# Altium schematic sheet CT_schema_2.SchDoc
size 314 x 312 mm
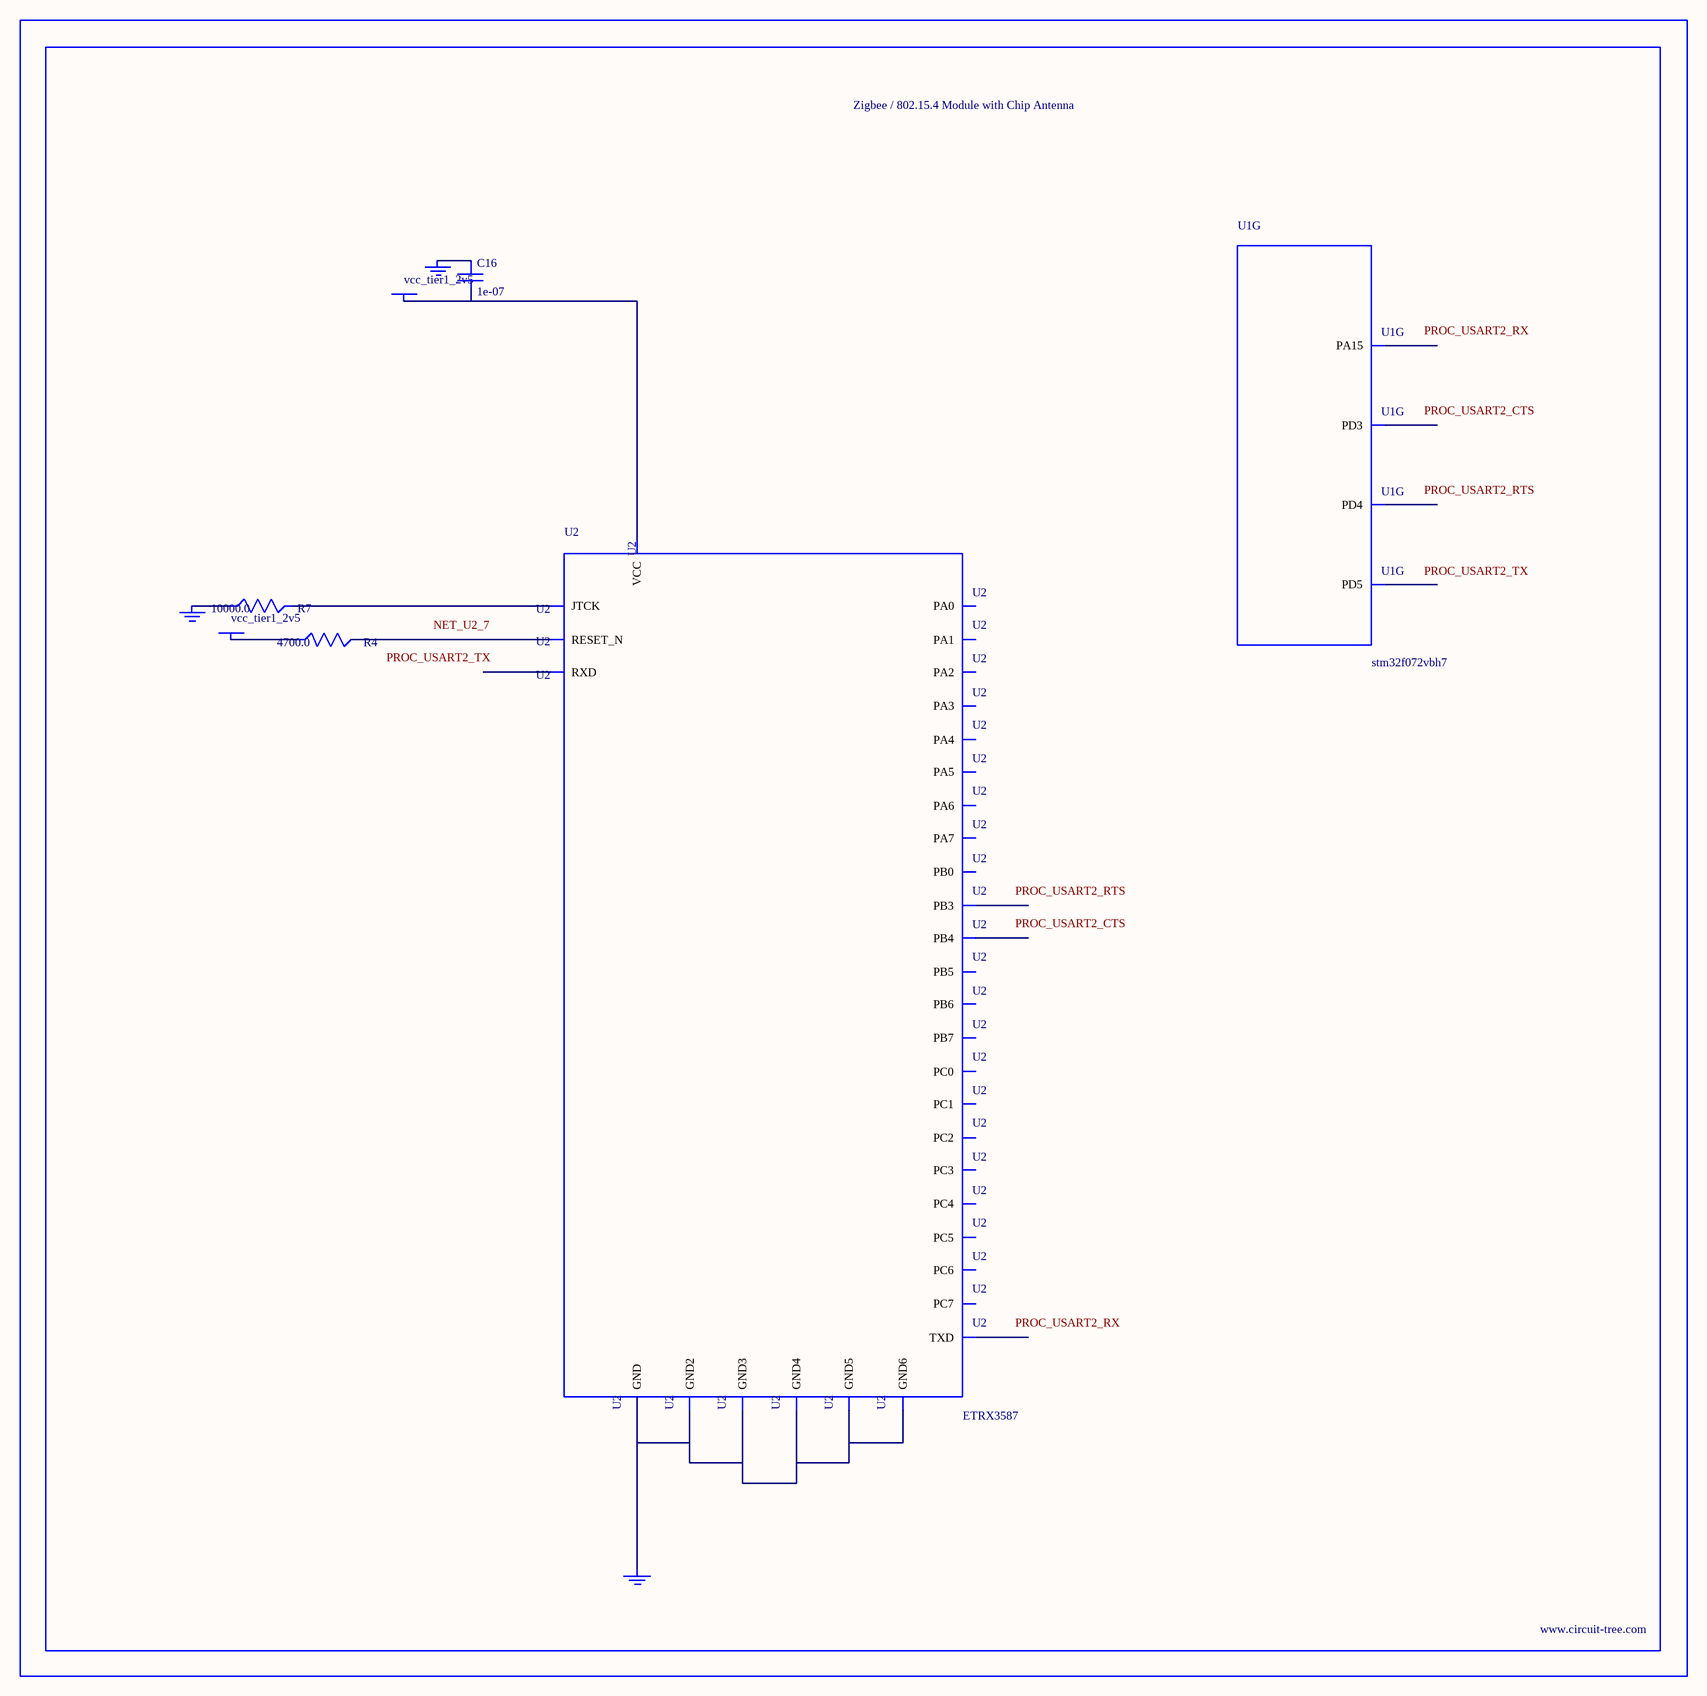
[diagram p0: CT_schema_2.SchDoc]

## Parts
BORDER1  (no value)
C16  1e-07  [C0402]
GND_INSTANCE_1_0  (no value)
GND_INSTANCE_1_1  (no value)
GND_INSTANCE_1_2  (no value)
POWER_INSTANCE_1_0  vcc_tier1_2v5
POWER_INSTANCE_1_1  vcc_tier1_2v5
R4  4700.0  [R0603]
R7  10000.0  [R0603]
U1  stm32f072vbh7  [UFBGA100]  (part G of 9)
U2  ETRX3587  [ETRX3587]

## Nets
NetC16_1: C16.1 GND_INSTANCE_1_1.0(GND)
NetC16_2: C16.2 POWER_INSTANCE_1_0.0(PWR) U2.32(VCC)
NetGND_INSTANCE_1_0_0: GND_INSTANCE_1_0.0(GND) R7.1
NetGND_INSTANCE_1_2_0: GND_INSTANCE_1_2.0(GND) U2.1(GND) U2.13(GND2) U2.19(GND3) U2.20(GND4) U2.31(GND5) U2.33(GND6)
NetPOWER_INSTANCE_1_1_0: POWER_INSTANCE_1_1.0(PWR) R4.1
NetR4_2: R4.2 U2.7(RESET_N)
NetR7_2: R7.2 U2.21(JTCK)

Not connected (* = marked no-connect by the designer): U1 A6(PD5) A9(PA15) B7(PD4) B8(PD3); U2 2(PC5) 3(PC6) 4(PC7) 5(PA7) 6(PB3) 8(PB4) 9(PA0) 10(PA1) 11(PA2) 12(PA3) 14(PA4) 15(PA5) 16(PA6) 17(TXD) 18(RXD) 22(PC2) 23(PC3) 24(PC4) 25(PB0) 26(PC1) 27(PC0) 28(PB7) 29(PB6) 30(PB5)

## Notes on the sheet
- Labels drawn without touching a wire or pin: NET_U2_7, PROC_USART2_CTS, PROC_USART2_RTS, PROC_USART2_RX, PROC_USART2_TX

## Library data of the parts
BORDER1 = BORDER_PAGE1
C16 = C0402C104K3RACTU
GND_INSTANCE_1_0-GND_INSTANCE_1_2 = GND
POWER_INSTANCE_1_0 POWER_INSTANCE_1_1 = PWR
R4 = RC0603JR-074K7L
R7 = RC0603JR-0710KL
